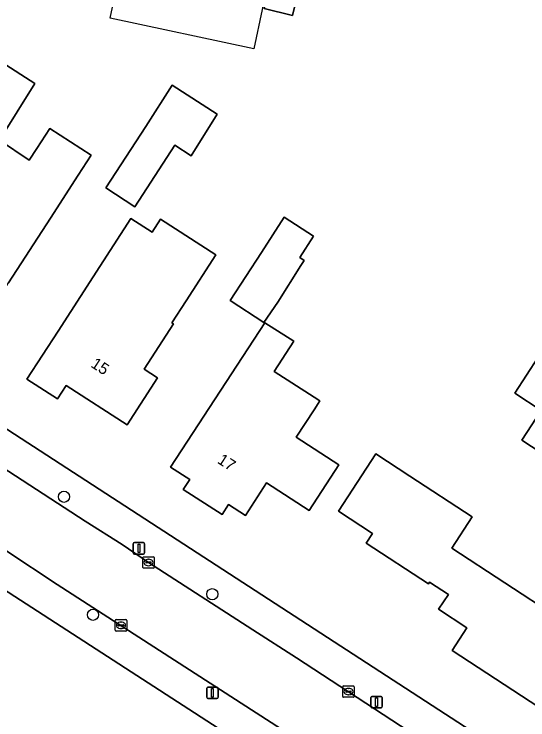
# Model space of a CAD drawing. Extents: x 161139 to 161601, y 381708 to 382245.
# Drawn here: x 161473.8 to 161518.7, y 382048.1 to 382109.7 of the extents above; entities that cross this region are included whole.
import ezdxf

# ---------------------------------------------------------------- set-up
doc = ezdxf.new("R2010")
doc.units = 0
for name, color, linetype in [('IMGEO_Boom', 7, 'Continuous'), ('IMGEO_Erf', 7, 'Continuous'), ('IMGEO_Kolk', 7, 'Continuous'), ('IMGEO_Lichtmast', 7, 'Continuous'), ('IMGEO_Pand', 7, 'Continuous'), ('IMGEO_Pand_nummerreeks', 7, 'Continuous'), ('IMGEO_Pand_vergunning_verleend', 7, 'Continuous'), ('IMGEO_Rijbaan_lokaal_open', 7, 'Continuous'), ('IMGEO_Voetpad_open', 7, 'Continuous')]:
    doc.layers.add(name, color=color, linetype=linetype)

msp = doc.modelspace()

# ---------------------------------------------------------------- linework, layer by layer
at = {"layer": 'IMGEO_Boom'}
for centre in [(161478.171, 382067.593), (161491.119, 382059.095), (161480.703, 382057.296)]:
    msp.add_circle(centre, 0.489, dxfattribs=at)
at = {"layer": 'IMGEO_Erf'}
for points in [[(161553.295, 382144.911), (161544.61, 382147.101), (161500, 382158.072), (161477.956, 382163.494), (161457.897, 382168.303), (161418.52, 382178.097), (161389.844, 382185.251), (161387.058, 382185.651), (161384.186, 382184.996), (161381.949, 382183.375), (161380.259, 382181.034), (161377.586, 382172.934), (161374.321, 382163.969), (161372.26, 382158.835), (161369.98, 382153.637), (161365.084, 382143.565), (161365.175, 382143.293), (161389.855, 382127.317), (161408.789, 382114.947), (161450.498, 382088.211), (161500, 382056.07), (161523.437, 382040.853), (161561.628, 382099.383), (161581.409, 382129.761)], [(161320.525, 382089.631), (161313.623, 382083.997), (161443.483, 382000), (161462.38, 381987.777), (161470.3, 382000), (161498.24, 382043.117), (161359.011, 382133.266)], [(161472.701, 382105.54), (161475.629, 382103.645), (161472.521, 382098.709), (161475.134, 382096.962), (161475.817, 382097.985), (161476.937, 382099.717), (161480.537, 382097.387), (161479.416, 382095.655), (161476.987, 382091.901), (161473.333, 382086.254)]]:
    msp.add_lwpolyline(points, dxfattribs=at)
for points in [[(161499.638, 382126.427), (161503.333, 382125.516), (161501.615, 382118.549), (161500.393, 382118.85), (161498.111, 382109.598), (161495.638, 382110.208)], [(161487.621, 382103.505), (161491.559, 382100.981), (161489.276, 382097.346), (161487.84, 382098.275), (161484.363, 382092.902), (161481.828, 382094.542), (161485.305, 382099.915)], [(161491.419, 382088.692), (161488.836, 382084.7), (161487.587, 382082.77), (161487.723, 382082.682), (161485.173, 382078.74), (161486.34, 382077.984), (161483.681, 382073.875), (161478.363, 382077.315), (161477.599, 382076.134), (161474.937, 382077.857), (161477.654, 382082.055), (161480.723, 382086.799), (161484.017, 382091.889), (161485.871, 382090.689), (161486.598, 382091.812)], [(161495.409, 382088.907), (161497.398, 382091.979), (161499.955, 382090.325), (161498.753, 382088.467), (161499.139, 382088.216), (161498.86, 382087.785), (161496.844, 382084.571), (161495.629, 382082.809), (161492.691, 382084.71)], [(161498.246, 382081.182), (161496.528, 382078.527), (161500, 382076.281), (161500.497, 382075.96), (161500, 382075.192), (161498.44, 382072.781), (161502.156, 382070.378), (161499.57, 382066.399), (161495.863, 382068.798), (161494.019, 382065.948), (161492.529, 382066.912), (161491.969, 382066.048), (161488.586, 382068.237), (161489.145, 382069.102), (161487.462, 382070.191), (161495.709, 382082.759)], [(161525.013, 382076.229), (161523.049, 382073.199), (161533.095, 382066.653), (161529.061, 382060.463), (161524.873, 382063.195), (161520.269, 382066.197), (161522.531, 382069.665), (161518.135, 382072.533), (161519.823, 382075.12), (161517.521, 382076.623), (161519.575, 382079.772), (161520.824, 382078.958)], [(161513.814, 382065.857), (161512.023, 382063.108), (161521.288, 382057.068), (161520.733, 382056.215), (161524.682, 382053.642), (161522.592, 382050.435), (161523.042, 382050.142), (161521.792, 382048.223), (161521.315, 382048.534), (161521.136, 382048.26), (161512.05, 382054.18), (161513.345, 382056.167), (161510.877, 382057.775), (161511.727, 382059.08), (161510.091, 382060.146), (161509.99, 382059.992), (161504.545, 382063.541), (161505.105, 382064.4), (161502.144, 382066.33), (161505.406, 382071.336), (161508.368, 382069.406)]]:
    msp.add_lwpolyline(points, close=True, dxfattribs=at)
at = {"layer": 'IMGEO_Kolk'}
for p, q in [((161485.053, 382061.434), (161485.053, 382062.286)), ((161485.128, 382062.36), (161485.98, 382062.36)), ((161486.054, 382062.286), (161486.054, 382061.434)), ((161485.312, 382061.854), (161485.312, 382061.866)), ((161485.75, 382061.817), (161485.352, 382061.817)), ((161485.355, 382061.903), (161485.753, 382061.903)), ((161485.564, 382061.58), (161485.539, 382061.58)), ((161485.541, 382062.14), (161485.566, 382062.14)), ((161485.796, 382061.866), (161485.796, 382061.854)), ((161485.98, 382061.36), (161485.128, 382061.36)), ((161482.65, 382055.951), (161482.65, 382056.803)), ((161482.725, 382056.877), (161483.577, 382056.877)), ((161483.138, 382056.657), (161483.163, 382056.657)), ((161483.651, 382056.803), (161483.651, 382055.951)), ((161482.909, 382056.371), (161482.909, 382056.383)), ((161483.347, 382056.334), (161482.949, 382056.334)), ((161482.952, 382056.42), (161483.35, 382056.42)), ((161483.161, 382056.097), (161483.136, 382056.097)), ((161483.393, 382056.383), (161483.393, 382056.371)), ((161483.577, 382055.877), (161482.725, 382055.877)), ((161502.582, 382051.097), (161503.434, 382051.097)), ((161502.507, 382050.171), (161502.507, 382051.023)), ((161502.766, 382050.591), (161502.766, 382050.603)), ((161503.204, 382050.554), (161502.806, 382050.554)), ((161502.809, 382050.64), (161503.207, 382050.64)), ((161502.995, 382050.877), (161503.02, 382050.877)), ((161503.25, 382050.603), (161503.25, 382050.591)), ((161503.508, 382051.023), (161503.508, 382050.171)), ((161503.434, 382050.097), (161502.582, 382050.097)), ((161503.018, 382050.317), (161502.993, 382050.317))]:
    msp.add_line(p, q, dxfattribs=at)
for points in [[(161485.053, 382061.434), (161485.053, 382062.286)], [(161485.128, 382062.36), (161485.98, 382062.36)], [(161486.054, 382062.286), (161486.054, 382061.434)], [(161485.98, 382061.36), (161485.128, 382061.36)], [(161482.65, 382055.951), (161482.65, 382056.803)], [(161482.725, 382056.877), (161483.577, 382056.877)], [(161483.651, 382056.803), (161483.651, 382055.951)], [(161483.577, 382055.877), (161482.725, 382055.877)], [(161502.582, 382051.097), (161503.434, 382051.097)], [(161502.507, 382050.171), (161502.507, 382051.023)], [(161503.508, 382051.023), (161503.508, 382050.171)], [(161503.434, 382050.097), (161502.582, 382050.097)]]:
    msp.add_lwpolyline(points, dxfattribs=at)
for centre, radius, start, end in [((161485.13, 382062.284), 0.0765, 91.55205, 178.44795), ((161485.13, 382062.284), 0.0765, 91.55205, 178.44795), ((161485.978, 382062.284), 0.0765, 1.55205, 88.44795), ((161485.978, 382062.284), 0.0765, 1.55205, 88.44795), ((161485.352, 382061.863), 0.0403, 85.87752, 175.75265), ((161485.349, 382061.853), 0.0366, 178.93798, 274.71019), ((161485.753, 382061.86), 0.043, 264.86636, 352.45326), ((161485.757, 382061.865), 0.0386, 1.73085, 96.63898), ((161485.13, 382061.436), 0.0765, 181.55205, 268.44795), ((161485.13, 382061.436), 0.0765, 181.55205, 268.44795), ((161485.978, 382061.436), 0.0765, 271.55205, 358.44795), ((161485.978, 382061.436), 0.0765, 271.55205, 358.44795), ((161482.727, 382056.801), 0.0765, 91.55205, 178.44795), ((161482.727, 382056.801), 0.0765, 91.55205, 178.44795), ((161483.575, 382056.801), 0.0765, 1.55205, 88.44795), ((161483.575, 382056.801), 0.0765, 1.55205, 88.44795), ((161482.949, 382056.38), 0.0403, 85.87752, 175.75265), ((161482.946, 382056.37), 0.0366, 178.93798, 274.71019), ((161483.35, 382056.377), 0.043, 264.86636, 352.45326), ((161483.354, 382056.382), 0.0386, 1.73085, 96.63898), ((161482.727, 382055.953), 0.0765, 181.55205, 268.44795), ((161482.727, 382055.953), 0.0765, 181.55205, 268.44795), ((161483.575, 382055.953), 0.0765, 271.55205, 358.44795), ((161483.575, 382055.953), 0.0765, 271.55205, 358.44795), ((161502.584, 382051.021), 0.0765, 91.55205, 178.44795), ((161502.584, 382051.021), 0.0765, 91.55205, 178.44795), ((161503.432, 382051.021), 0.0765, 1.55205, 88.44795), ((161503.432, 382051.021), 0.0765, 1.55205, 88.44795), ((161502.806, 382050.6), 0.0403, 85.87752, 175.75265), ((161502.803, 382050.59), 0.0366, 178.93798, 274.71019), ((161503.207, 382050.597), 0.043, 264.86636, 352.45326), ((161503.211, 382050.602), 0.0386, 1.73085, 96.63898), ((161502.584, 382050.173), 0.0765, 181.55205, 268.44795), ((161502.584, 382050.173), 0.0765, 181.55205, 268.44795), ((161503.432, 382050.173), 0.0765, 271.55205, 358.44795), ((161503.432, 382050.173), 0.0765, 271.55205, 358.44795)]:
    msp.add_arc(centre, radius, start, end, dxfattribs=at)
for centre, major_axis, ratio, start_param, end_param in [((161485.54, 382061.86), (-0.387, 0.002), 0.722429, 4.712389, 7.853982), ((161485.565, 382061.86), (-0.39, 0.002), 0.717154, 1.570796, 4.712389), ((161483.137, 382056.377), (-0.387, 0.002), 0.722429, 4.712389, 7.853982), ((161483.162, 382056.377), (-0.39, 0.002), 0.717154, 1.570796, 4.712389), ((161502.994, 382050.597), (-0.387, 0.002), 0.722429, 4.712389, 7.853982), ((161503.019, 382050.597), (-0.39, 0.002), 0.717154, 1.570796, 4.712389)]:
    msp.add_ellipse(centre, major_axis=major_axis, ratio=ratio, start_param=start_param, end_param=end_param, dxfattribs=at)
at = {"layer": 'IMGEO_Lichtmast'}
for p, q in [((161484.225, 382062.697), (161484.225, 382063.497)), ((161484.225, 382063.497), (161484.225, 382062.697)), ((161484.325, 382063.597), (161485.115, 382063.597)), ((161485.115, 382063.597), (161484.325, 382063.597)), ((161485.215, 382063.497), (161485.215, 382062.697)), ((161485.215, 382062.697), (161485.215, 382063.497)), ((161485.115, 382062.597), (161484.325, 382062.597)), ((161484.325, 382062.597), (161485.115, 382062.597)), ((161490.63, 382050.094), (161490.63, 382050.894)), ((161490.63, 382050.894), (161490.63, 382050.094)), ((161490.73, 382050.994), (161491.52, 382050.994)), ((161491.52, 382050.994), (161490.73, 382050.994)), ((161491.62, 382050.894), (161491.62, 382050.094)), ((161491.62, 382050.094), (161491.62, 382050.894)), ((161491.52, 382049.994), (161490.73, 382049.994)), ((161490.73, 382049.994), (161491.52, 382049.994)), ((161504.96, 382049.28), (161504.96, 382050.08)), ((161504.96, 382050.08), (161504.96, 382049.28)), ((161505.06, 382050.18), (161505.85, 382050.18)), ((161505.85, 382050.18), (161505.06, 382050.18)), ((161505.95, 382050.08), (161505.95, 382049.28)), ((161505.95, 382049.28), (161505.95, 382050.08)), ((161505.85, 382049.18), (161505.06, 382049.18)), ((161505.06, 382049.18), (161505.85, 382049.18))]:
    msp.add_line(p, q, dxfattribs=at)
for points in [[(161484.645, 382063.472), (161484.795, 382063.472), (161484.795, 382062.722), (161484.645, 382062.722), (161484.645, 382063.472)], [(161491.05, 382050.869), (161491.2, 382050.869), (161491.2, 382050.119), (161491.05, 382050.119), (161491.05, 382050.869)], [(161505.38, 382050.055), (161505.53, 382050.055), (161505.53, 382049.305), (161505.38, 382049.305), (161505.38, 382050.055)]]:
    msp.add_lwpolyline(points, dxfattribs=at)
for centre, start, end in [((161484.325, 382063.497), 90, 180), ((161484.325, 382063.497), 90, 180), ((161485.115, 382063.497), 0, 90), ((161485.115, 382063.497), 360, 90), ((161484.325, 382062.697), 180, 270), ((161484.325, 382062.697), 180, 270), ((161485.115, 382062.697), 270, 0), ((161485.115, 382062.697), 270, 0), ((161490.73, 382050.894), 90, 180), ((161490.73, 382050.894), 90, 180), ((161491.52, 382050.894), 0, 90), ((161491.52, 382050.894), 360, 90), ((161490.73, 382050.094), 180, 270), ((161490.73, 382050.094), 180, 270), ((161491.52, 382050.094), 270, 0), ((161491.52, 382050.094), 270, 0), ((161505.06, 382050.08), 90, 180), ((161505.06, 382050.08), 90, 180), ((161505.85, 382050.08), 0, 90), ((161505.85, 382050.08), 360, 90), ((161505.06, 382049.28), 180, 270), ((161505.06, 382049.28), 180, 270), ((161505.85, 382049.28), 270, 0), ((161505.85, 382049.28), 270, 0)]:
    msp.add_arc(centre, 0.1, start, end, dxfattribs=at)
at = {"layer": 'IMGEO_Pand'}
for points in [[(161495.638, 382110.208), (161498.111, 382109.598), (161500.393, 382118.85), (161501.615, 382118.549), (161503.333, 382125.516), (161499.638, 382126.427)], [(161479.416, 382095.655), (161480.537, 382097.387), (161476.937, 382099.717), (161475.817, 382097.985), (161475.134, 382096.962), (161472.521, 382098.709), (161475.629, 382103.645), (161472.701, 382105.54), (161467.455, 382097.44), (161469.966, 382095.815), (161463.023, 382085.085), (161467.256, 382082.346), (161468.115, 382083.674), (161470.617, 382082.055), (161473.333, 382086.254), (161476.987, 382091.901)], [(161485.305, 382099.915), (161481.828, 382094.542), (161484.363, 382092.902), (161487.84, 382098.275), (161489.276, 382097.346), (161491.559, 382100.981), (161487.621, 382103.505)], [(161485.871, 382090.689), (161484.017, 382091.889), (161480.723, 382086.799), (161477.654, 382082.055), (161474.937, 382077.857), (161477.599, 382076.134), (161478.363, 382077.315), (161483.681, 382073.875), (161486.34, 382077.984), (161485.173, 382078.74), (161487.723, 382082.682), (161487.587, 382082.77), (161488.836, 382084.7), (161491.419, 382088.692), (161486.598, 382091.812)], [(161498.86, 382087.785), (161499.139, 382088.216), (161498.753, 382088.467), (161499.955, 382090.325), (161497.398, 382091.979), (161495.409, 382088.907), (161492.691, 382084.71), (161495.629, 382082.809), (161496.844, 382084.571)], [(161500, 382075.192), (161500.497, 382075.96), (161500, 382076.281), (161496.528, 382078.527), (161498.246, 382081.182), (161495.709, 382082.759), (161487.462, 382070.191), (161489.145, 382069.102), (161488.586, 382068.237), (161491.969, 382066.048), (161492.529, 382066.912), (161494.019, 382065.948), (161495.863, 382068.798), (161499.57, 382066.399), (161502.156, 382070.378), (161498.44, 382072.781)], [(161524.873, 382063.195), (161529.061, 382060.463), (161533.095, 382066.653), (161523.049, 382073.199), (161525.013, 382076.229), (161520.824, 382078.958), (161519.575, 382079.772), (161517.521, 382076.623), (161519.823, 382075.12), (161518.135, 382072.533), (161522.531, 382069.665), (161520.269, 382066.197)], [(161512.023, 382063.108), (161513.814, 382065.857), (161508.368, 382069.406), (161505.406, 382071.336), (161502.144, 382066.33), (161505.105, 382064.4), (161504.545, 382063.541), (161509.99, 382059.992), (161510.091, 382060.146), (161511.727, 382059.08), (161510.877, 382057.775), (161513.345, 382056.167), (161512.05, 382054.18), (161521.136, 382048.26), (161521.315, 382048.534), (161521.792, 382048.223), (161523.042, 382050.142), (161522.592, 382050.435), (161524.682, 382053.642), (161520.733, 382056.215), (161521.288, 382057.068)]]:
    msp.add_lwpolyline(points, close=True, dxfattribs=at)
at = {"layer": 'IMGEO_Pand_vergunning_verleend'}
msp.add_lwpolyline([(161496.204, 382113.578), (161494.74, 382106.686), (161482.199, 382109.349), (161483.663, 382116.241)], close=True, dxfattribs=at)
at = {"layer": 'IMGEO_Rijbaan_lokaal_open'}
for points in [[(161521.765, 382038.348), (161512.078, 382044.654), (161498.469, 382053.534), (161494.669, 382055.998), (161485.554, 382061.86), (161483.251, 382063.426), (161480.028, 382065.466), (161471.488, 382070.983), (161468.287, 382073.003), (161467.324, 382073.702), (161460.192, 382078.284), (161453.24, 382082.778), (161444.055, 382088.754), (161440.905, 382090.804), (161426.931, 382099.82), (161420.597, 382103.968), (161416.21, 382106.739), (161403.197, 382115.21)], [(161398.574, 382111.058), (161401.761, 382109.008), (161415.306, 382100.289), (161421.669, 382096.147), (161435.549, 382087.163), (161442.527, 382082.644), (161453.542, 382075.54), (161460.477, 382071.037), (161473.195, 382062.836), (161477.592, 382059.945), (161498.051, 382046.741), (161499.796, 382045.589), (161510.796, 382038.454), (161522.385, 382030.943)]]:
    msp.add_lwpolyline(points, dxfattribs=at)
at = {"layer": 'IMGEO_Voetpad_open'}
for points in [[(161421.669, 382096.147), (161415.306, 382100.289), (161401.761, 382109.008), (161398.574, 382111.058), (161389.569, 382116.981), (161386.277, 382119.018), (161382.915, 382121.211), (161379.746, 382123.279), (161360.833, 382135.554), (161359.011, 382133.266), (161498.24, 382043.117), (161500.799, 382041.385)], [(161403.197, 382115.21), (161416.21, 382106.739), (161420.597, 382103.968), (161426.931, 382099.82), (161440.905, 382090.804), (161444.055, 382088.754), (161453.24, 382082.778), (161460.192, 382078.284), (161467.324, 382073.702), (161468.287, 382073.003), (161471.488, 382070.983), (161480.028, 382065.466), (161483.251, 382063.426), (161485.554, 382061.86), (161494.669, 382055.998), (161498.469, 382053.534), (161512.078, 382044.654), (161521.765, 382038.348), (161525.596, 382035.854), (161527.949, 382034.358)], [(161499.883, 382045.525), (161499.84, 382045.557), (161499.796, 382045.589), (161498.051, 382046.741), (161477.592, 382059.945), (161473.195, 382062.836), (161460.477, 382071.037), (161453.542, 382075.54), (161442.527, 382082.644), (161435.549, 382087.163), (161421.669, 382096.147)], [(161528.309, 382037.772), (161526.784, 382038.653), (161525.518, 382039.495), (161523.437, 382040.853), (161500, 382056.07), (161450.498, 382088.211)]]:
    msp.add_lwpolyline(points, dxfattribs=at)

# ---------------------------------------------------------------- texts
at = {"layer": 'IMGEO_Pand_nummerreeks'}
for s, rotation, p in [('15', 327.1028, (161480.442, 382078.971)), ('17', 327.09503, (161491.492, 382070.584))]:
    msp.add_text(s, height=1, rotation=rotation, dxfattribs=at).set_placement(p)

doc.saveas('drawing.dxf')
